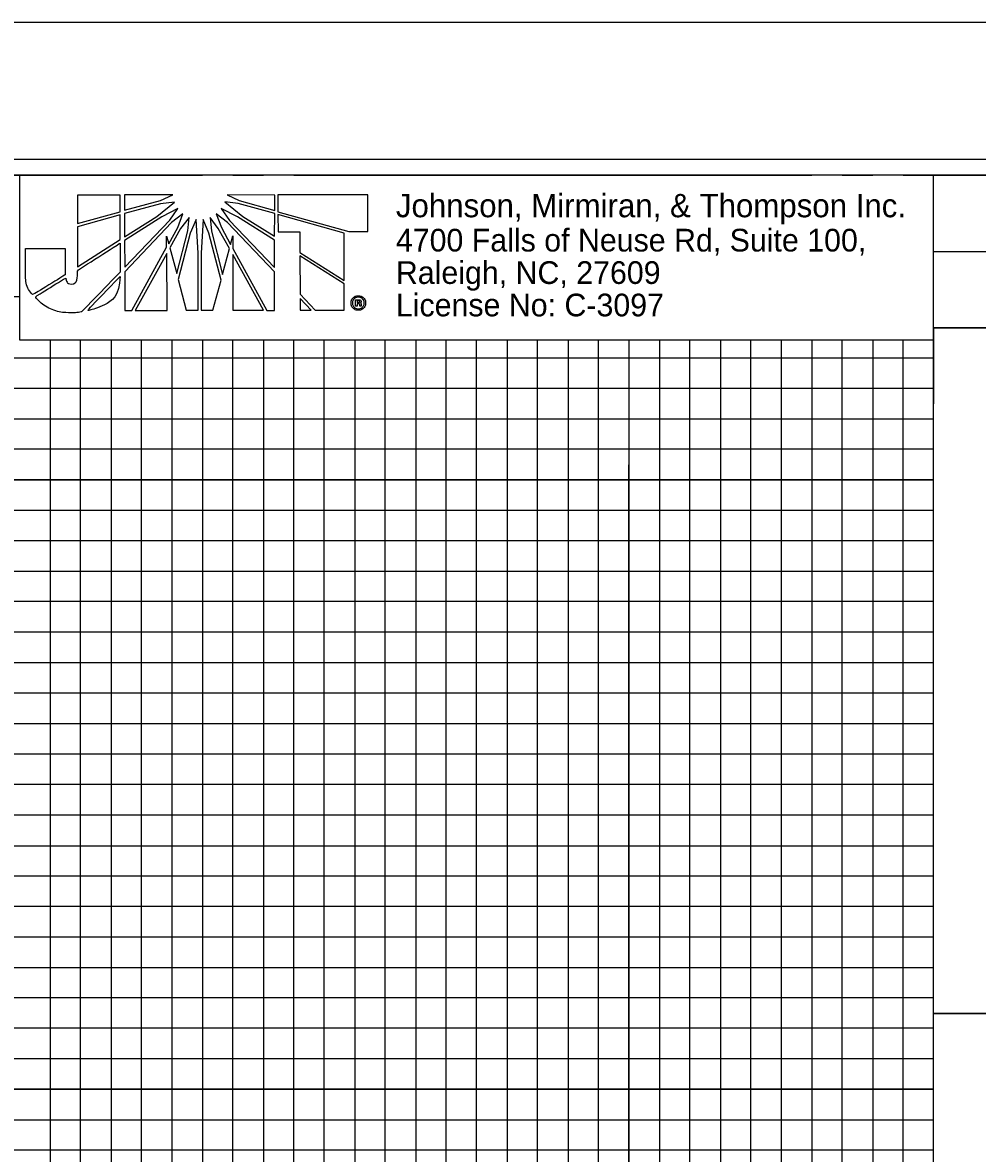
# Model space of a CAD drawing. Extents: x 1650661 to 1652901, y 832691 to 833791.
# Drawn here: x 1652354.8 to 1652511.5, y 833605.5 to 833791 of the extents above; entities that cross this region are included whole.
import ezdxf

# ---------------------------------------------------------------- set-up
doc = ezdxf.new("R2010")
doc.units = 0
for name, color, linetype in [('Prop Dimension Text', 7, 'Continuous'), ('Sheet Cutting Line CELL', 7, 'Continuous'), ('Sheet DOT Grid CELL', 7, 'Continuous'), ('Sheet Plan CELL', 7, 'Continuous'), ('Sheet Plot Border Inside CELL', 7, 'Continuous'), ('Sheet Plot Border Outside CELL', 7, 'Continuous'), ('Sheet Profile CELL', 7, 'Continuous'), ('Sheet Profile Grid Major CELL', 7, 'Continuous'), ('Sheet Profile Grid Middle CELL', 7, 'Continuous'), ('Sheet Profile Grid Minor CELL', 7, 'Continuous'), ('Sheet Sticker Exception Certification CELL', 7, 'Continuous')]:
    doc.layers.add(name, color=color, linetype=linetype)

msp = doc.modelspace()

# ---------------------------------------------------------------- linework, layer by layer
at = {"layer": 'Prop Dimension Text'}
for p, q in [((1652370.79, 833762.71), (1652363.77, 833762.7)), ((1652363.77, 833762.7), (1652363.77, 833758.05)), ((1652370.79, 833760), (1652370.79, 833762.71)), ((1652379.41, 833762.75), (1652371.52, 833762.75)), ((1652371.52, 833762.75), (1652371.52, 833760.23)), ((1652377.4, 833761.86), (1652379.41, 833762.75)), ((1652396.14, 833762.73), (1652388.35, 833762.76)), ((1652388.35, 833762.76), (1652390.32, 833761.84)), ((1652396.14, 833760.21), (1652396.14, 833762.73)), ((1652411.43, 833762.78), (1652396.68, 833762.77)), ((1652396.68, 833762.77), (1652396.68, 833760.06)), ((1652411.44, 833756.74), (1652411.43, 833762.78)), ((1652371.52, 833760.23), (1652377.4, 833761.86)), ((1652377.4, 833761.31), (1652371.52, 833759.69)), ((1652376.79, 833759.23), (1652379.69, 833761.59)), ((1652379.69, 833761.59), (1652377.4, 833761.31)), ((1652380.27, 833760.51), (1652377.6, 833759.15)), ((1652378.92, 833758.61), (1652380.27, 833760.51)), ((1652387.35, 833760.51), (1652388.71, 833758.58)), ((1652390.06, 833759.16), (1652387.35, 833760.51)), ((1652387.96, 833761.6), (1652390.9, 833759.2)), ((1652390.13, 833761.33), (1652387.96, 833761.6)), ((1652396.14, 833759.68), (1652390.13, 833761.33)), ((1652390.32, 833761.84), (1652396.14, 833760.21)), ((1652363.77, 833758.05), (1652370.79, 833760)), ((1652370.79, 833759.49), (1652363.77, 833757.52)), ((1652370.79, 833755.43), (1652370.79, 833759.49)), ((1652371.52, 833759.69), (1652371.52, 833755.89)), ((1652371.52, 833755.89), (1652376.79, 833759.23)), ((1652377.6, 833759.15), (1652371.52, 833755.28)), ((1652381.08, 833759.66), (1652379.22, 833758.22)), ((1652380.23, 833757.42), (1652381.08, 833759.66)), ((1652382.09, 833759.04), (1652380.7, 833757.25)), ((1652381.9, 833756.87), (1652382.09, 833759.04)), ((1652383.25, 833758.73), (1652382.29, 833756.48)), ((1652383.56, 833753.19), (1652383.25, 833758.73)), ((1652384.41, 833758.73), (1652384.05, 833753.19)), ((1652385.34, 833756.48), (1652384.41, 833758.73)), ((1652385.53, 833759.04), (1652385.77, 833756.8)), ((1652386.89, 833757.26), (1652385.53, 833759.04)), ((1652386.53, 833759.67), (1652387.39, 833757.42)), ((1652388.39, 833758.23), (1652386.53, 833759.67)), ((1652396.1, 833755.33), (1652390.06, 833759.16)), ((1652390.9, 833759.2), (1652396.1, 833755.96)), ((1652396.1, 833755.96), (1652396.14, 833759.68)), ((1652396.68, 833760.06), (1652396.68, 833759.98)), ((1652396.68, 833759.98), (1652408.3, 833756.74)), ((1652396.68, 833759.56), (1652396.68, 833759.52)), ((1652407.56, 833756.47), (1652396.68, 833759.56)), ((1652396.68, 833759.52), (1652396.69, 833756.69)), ((1652363.77, 833757.52), (1652363.78, 833750.97)), ((1652371.53, 833750.9), (1652378.92, 833758.61)), ((1652379.22, 833758.22), (1652371.53, 833750.16)), ((1652378.76, 833754.74), (1652380.23, 833757.42)), ((1652380.7, 833757.25), (1652378.96, 833754.08)), ((1652380.09, 833749.87), (1652381.9, 833756.87)), ((1652385.77, 833756.8), (1652387.59, 833749.71)), ((1652388.71, 833753.97), (1652386.89, 833757.26)), ((1652387.39, 833757.42), (1652388.89, 833754.63)), ((1652396.1, 833750.11), (1652388.39, 833758.23)), ((1652388.71, 833758.58), (1652396.1, 833750.84)), ((1652363.78, 833750.97), (1652370.79, 833755.43)), ((1652371.52, 833755.28), (1652371.53, 833750.9)), ((1652378.41, 833754.16), (1652378.41, 833756.01)), ((1652378.41, 833756.01), (1652378.76, 833754.74)), ((1652382.29, 833756.48), (1652380.32, 833748.89)), ((1652387.36, 833748.78), (1652385.34, 833756.48)), ((1652388.89, 833754.63), (1652389.25, 833756.02)), ((1652389.25, 833756.02), (1652389.25, 833753.97)), ((1652396.1, 833750.84), (1652396.1, 833755.33)), ((1652396.69, 833756.69), (1652400.29, 833756.69)), ((1652400.29, 833756.69), (1652400.29, 833753.32)), ((1652407.57, 833748.72), (1652407.56, 833756.47)), ((1652408.3, 833756.74), (1652411.44, 833756.74)), ((1652372.69, 833743.79), (1652378.41, 833754.16)), ((1652378.42, 833753.15), (1652373.24, 833743.79)), ((1652378.47, 833743.8), (1652378.42, 833753.15)), ((1652378.96, 833754.08), (1652380.09, 833749.87)), ((1652383.57, 833743.84), (1652383.56, 833753.19)), ((1652384.05, 833753.19), (1652384.06, 833743.84)), ((1652387.59, 833749.71), (1652388.71, 833753.97)), ((1652389.25, 833753.97), (1652394.87, 833743.81)), ((1652400.29, 833753.32), (1652407.57, 833748.72)), ((1652394.29, 833743.85), (1652389.25, 833752.97)), ((1652389.25, 833752.97), (1652389.26, 833743.84)), ((1652400.29, 833752.74), (1652400.3, 833746.47)), ((1652407.57, 833748.18), (1652400.29, 833752.74)), ((1652371.53, 833750.16), (1652371.53, 833743.79)), ((1652396.11, 833743.81), (1652396.1, 833750.11)), ((1652380.32, 833748.89), (1652381.64, 833743.83)), ((1652386.01, 833743.84), (1652387.36, 833748.78)), ((1652407.57, 833743.82), (1652407.57, 833748.18)), ((1652400.3, 833746.47), (1652402.81, 833743.82)), ((1652402.12, 833743.82), (1652400.3, 833745.78)), ((1652400.3, 833745.78), (1652400.3, 833743.82)), ((1652409.86, 833746.19), (1652409.86, 833745.97)), ((1652409.86, 833745.97), (1652409.86, 833746.19)), ((1652371.53, 833743.79), (1652372.69, 833743.79)), ((1652373.24, 833743.79), (1652378.47, 833743.8)), ((1652381.64, 833743.83), (1652383.57, 833743.84)), ((1652384.06, 833743.84), (1652386.01, 833743.84)), ((1652389.26, 833743.84), (1652394.29, 833743.85)), ((1652394.87, 833743.81), (1652396.11, 833743.81)), ((1652400.3, 833743.82), (1652402.12, 833743.82)), ((1652402.81, 833743.82), (1652407.57, 833743.82)), ((1652409.42, 833744.49), (1652409.42, 833745.56)), ((1652409.42, 833745.56), (1652409.86, 833745.56)), ((1652409.66, 833744.49), (1652409.42, 833744.49)), ((1652409.86, 833745.36), (1652409.66, 833745.36)), ((1652409.66, 833745.36), (1652409.66, 833745.1)), ((1652409.66, 833745.1), (1652409.86, 833745.1)), ((1652409.86, 833744.91), (1652409.66, 833744.91)), ((1652409.66, 833744.91), (1652409.66, 833744.49)), ((1652409.86, 833745.56), (1652409.86, 833745.36)), ((1652409.86, 833745.36), (1652409.86, 833745.56)), ((1652409.86, 833745.56), (1652409.92, 833745.56)), ((1652409.89, 833745.36), (1652409.86, 833745.36)), ((1652409.86, 833745.1), (1652409.86, 833744.91)), ((1652409.86, 833744.91), (1652409.86, 833745.1)), ((1652409.86, 833745.1), (1652409.87, 833745.1)), ((1652409.87, 833744.91), (1652409.86, 833744.91)), ((1652409.86, 833744.07), (1652409.86, 833743.83)), ((1652409.86, 833743.83), (1652409.86, 833744.07)), ((1652409.86, 833744.07), (1652409.87, 833744.07)), ((1652409.87, 833743.83), (1652409.86, 833743.83))]:
    msp.add_line(p, q, dxfattribs=at)
msp.add_lwpolyline([(1652354.28, 833738.96), (1652504.23, 833738.96), (1652504.23, 833766.02), (1652354.28, 833766.02)], close=True, dxfattribs=at)
for points in [[(1652363.77, 833758.05), (1652370.79, 833760), (1652370.79, 833762.71), (1652363.77, 833762.7), (1652363.77, 833758.05)], [(1652377.4, 833761.86), (1652379.41, 833762.75), (1652371.52, 833762.75), (1652371.52, 833760.23), (1652377.4, 833761.86)], [(1652390.32, 833761.84), (1652396.14, 833760.21), (1652396.14, 833762.73), (1652388.35, 833762.76), (1652390.32, 833761.84)], [(1652411.43, 833762.78), (1652396.68, 833762.77), (1652396.68, 833760.06), (1652396.68, 833759.98), (1652408.3, 833756.74), (1652411.44, 833756.74), (1652411.43, 833762.78)], [(1652371.52, 833759.69), (1652371.52, 833755.89), (1652376.79, 833759.23), (1652379.69, 833761.59), (1652377.4, 833761.31), (1652371.52, 833759.69)], [(1652371.52, 833755.28), (1652371.53, 833750.9), (1652378.92, 833758.61), (1652380.27, 833760.51), (1652377.6, 833759.15), (1652371.52, 833755.28)], [(1652387.35, 833760.51), (1652388.71, 833758.58), (1652396.1, 833750.84), (1652396.1, 833755.33), (1652390.06, 833759.16), (1652387.35, 833760.51)], [(1652387.96, 833761.6), (1652390.9, 833759.2), (1652396.1, 833755.96), (1652396.14, 833759.68), (1652390.13, 833761.33), (1652387.96, 833761.6)], [(1652363.78, 833750.97), (1652370.79, 833755.43), (1652370.79, 833759.49), (1652363.77, 833757.52), (1652363.78, 833750.97)], [(1652381.08, 833759.66), (1652379.22, 833758.22), (1652371.53, 833750.16), (1652371.53, 833743.79), (1652372.69, 833743.79), (1652378.41, 833754.16), (1652378.41, 833756.01), (1652378.76, 833754.74), (1652380.23, 833757.42), (1652381.08, 833759.66)], [(1652382.09, 833759.04), (1652380.7, 833757.25), (1652378.96, 833754.08), (1652380.09, 833749.87), (1652381.9, 833756.87), (1652382.09, 833759.04)], [(1652382.29, 833756.48), (1652380.32, 833748.89), (1652381.64, 833743.83), (1652383.57, 833743.84), (1652383.56, 833753.19), (1652383.25, 833758.73), (1652382.29, 833756.48)], [(1652384.41, 833758.73), (1652384.05, 833753.19), (1652384.06, 833743.84), (1652386.01, 833743.84), (1652387.36, 833748.78), (1652385.34, 833756.48), (1652384.41, 833758.73)], [(1652385.53, 833759.04), (1652385.77, 833756.8), (1652387.59, 833749.71), (1652388.71, 833753.97), (1652386.89, 833757.26), (1652385.53, 833759.04)], [(1652386.53, 833759.67), (1652387.39, 833757.42), (1652388.89, 833754.63), (1652389.25, 833756.02), (1652389.25, 833753.97), (1652394.87, 833743.81), (1652396.11, 833743.81), (1652396.1, 833750.11), (1652388.39, 833758.23), (1652386.53, 833759.67)], [(1652396.68, 833759.56), (1652396.68, 833759.52), (1652396.69, 833756.69), (1652400.29, 833756.69), (1652400.29, 833753.32), (1652407.57, 833748.72), (1652407.56, 833756.47), (1652396.68, 833759.56)], [(1652373.24, 833743.79), (1652378.47, 833743.8), (1652378.42, 833753.15), (1652373.24, 833743.79)], [(1652389.26, 833743.84), (1652394.29, 833743.85), (1652389.25, 833752.97), (1652389.26, 833743.84)], [(1652400.29, 833752.74), (1652400.3, 833746.47), (1652402.81, 833743.82), (1652407.57, 833743.82), (1652407.57, 833748.18), (1652400.29, 833752.74), (1652400.29, 833752.74)], [(1652400.3, 833743.82), (1652400.3, 833743.82), (1652402.12, 833743.82), (1652400.3, 833745.78), (1652400.3, 833743.82)], [(1652410.33, 833744.74), (1652410.33, 833744.68), (1652410.33, 833744.64), (1652410.33, 833744.61), (1652410.36, 833744.49), (1652410.14, 833744.49)]]:
    msp.add_lwpolyline(points, dxfattribs=at)
for points, degree in [([(1652361.76, 833753.98), (1652361.76, 833753.98), (1652355.27, 833753.98), (1652355.27, 833753.98), (1652355.27, 833753.98), (1652355.27, 833749.91), (1652355.27, 833749.91), (1652355.27, 833749.91), (1652355.27, 833749.48), (1652355.27, 833749.48), (1652355.27, 833748.21), (1652355.69, 833747.2), (1652356.43, 833746.36), (1652356.43, 833746.36), (1652361.77, 833749.6), (1652361.77, 833749.69), (1652361.77, 833749.69), (1652361.76, 833753.98), (1652361.76, 833753.98)], 3), ([(1652362.78, 833748.13), (1652362.36, 833748.13), (1652362, 833748.37), (1652361.85, 833749.14), (1652361.85, 833749.14), (1652356.81, 833746.02), (1652356.81, 833746.02), (1652358.37, 833744.39), (1652360.85, 833743.42), (1652362.94, 833743.42), (1652363.49, 833743.42), (1652363.9, 833743.47), (1652364.48, 833743.59), (1652364.48, 833743.59), (1652370.8, 833750.12), (1652370.8, 833750.12), (1652370.8, 833750.12), (1652370.79, 833754.85), (1652370.79, 833754.85), (1652370.79, 833754.85), (1652363.78, 833750.38), (1652363.78, 833750.38), (1652363.78, 833748.61), (1652363.35, 833748.14), (1652362.78, 833748.13)], 3), ([(1652362.78, 833748.13), (1652362.36, 833748.13), (1652362, 833748.37), (1652361.85, 833749.14), (1652361.85, 833749.14), (1652356.81, 833746.02), (1652356.81, 833746.02), (1652358.37, 833744.39), (1652360.85, 833743.42), (1652362.94, 833743.42), (1652363.49, 833743.42), (1652363.9, 833743.47), (1652364.48, 833743.59), (1652364.48, 833743.59), (1652370.8, 833750.12), (1652370.8, 833750.12), (1652370.8, 833750.12), (1652370.79, 833754.85), (1652370.79, 833754.85), (1652370.79, 833754.85), (1652363.78, 833750.38), (1652363.78, 833750.38), (1652363.78, 833748.61), (1652363.35, 833748.14), (1652362.78, 833748.13)], 3), ([(1652370.8, 833749.38), (1652370.8, 833749.38), (1652365.34, 833743.74), (1652365.34, 833743.74), (1652368.01, 833744.4), (1652370.68, 833746.17), (1652370.8, 833749.38)], 3), ([(1652409.86, 833743.83), (1652409.54, 833743.83), (1652409.25, 833743.95), (1652409.02, 833744.18), (1652408.78, 833744.41), (1652408.67, 833744.69), (1652408.67, 833745.02), (1652408.67, 833745.35), (1652408.78, 833745.64), (1652409.02, 833745.85), (1652409.25, 833746.08), (1652409.52, 833746.19), (1652409.86, 833746.19)], 3), ([(1652409.86, 833745.97), (1652409.59, 833745.97), (1652409.37, 833745.88), (1652409.18, 833745.71), (1652409, 833745.52), (1652408.9, 833745.29), (1652408.9, 833745.02), (1652408.9, 833744.76), (1652409, 833744.53), (1652409.18, 833744.34), (1652409.37, 833744.16), (1652409.59, 833744.07), (1652409.86, 833744.07)], 3), ([(1652409.86, 833746.19), (1652410.19, 833746.19), (1652410.47, 833746.08), (1652410.7, 833745.85), (1652410.94, 833745.64), (1652411.06, 833745.36), (1652411.06, 833745.03)], 3), ([(1652409.87, 833744.07), (1652410.13, 833744.07), (1652410.35, 833744.16), (1652410.54, 833744.34), (1652410.72, 833744.53), (1652410.82, 833744.76), (1652410.82, 833745.03), (1652410.82, 833745.29), (1652410.72, 833745.52), (1652410.54, 833745.71), (1652410.35, 833745.88), (1652410.13, 833745.97), (1652409.86, 833745.97)], 3), ([(1652409.87, 833745.1), (1652410.02, 833745.1), (1652410.1, 833745.15), (1652410.1, 833745.24), (1652410.1, 833745.32), (1652410.03, 833745.36), (1652409.89, 833745.36)], 3), ([(1652411.06, 833745.03), (1652411.06, 833744.69), (1652410.94, 833744.41), (1652410.72, 833744.18), (1652410.48, 833743.95), (1652410.2, 833743.83), (1652409.87, 833743.83)], 3), ([(1652410.05, 833744.87), (1652410.02, 833744.89), (1652409.96, 833744.91), (1652409.87, 833744.91)], 2), ([(1652409.92, 833745.56), (1652410.2, 833745.56), (1652410.33, 833745.45), (1652410.33, 833745.24), (1652410.33, 833745.14), (1652410.3, 833745.06), (1652410.21, 833745)], 3), ([(1652410.14, 833744.49), (1652410.11, 833744.55), (1652410.09, 833744.61), (1652410.09, 833744.68), (1652410.09, 833744.78), (1652410.08, 833744.84), (1652410.05, 833744.87)], 3), ([(1652410.21, 833745), (1652410.28, 833744.97), (1652410.32, 833744.88), (1652410.33, 833744.74)], 2)]:
    msp.add_open_spline(points, degree=degree, dxfattribs=at)
at = {"layer": 'Sheet Cutting Line CELL'}
msp.add_line((1652721.28, 833791.02), (1651037.28, 833791.02), dxfattribs=at)
at = {"layer": 'Sheet DOT Grid CELL'}
for p, q in [((1652404.28, 833266.02), (1652404.28, 833718.48)), ((1652454.28, 833266.02), (1652454.28, 833718.48)), ((1652504.23, 833716.02), (1651204.28, 833716.02)), ((1652504.23, 833666.02), (1651204.28, 833666.02)), ((1652504.28, 833266.02), (1652504.28, 833628.47)), ((1652504.28, 833616.02), (1651204.28, 833616.02))]:
    msp.add_line(p, q, dxfattribs=at)
at = {"layer": 'Sheet Plan CELL'}
msp.add_line((1652504.23, 833740.94), (1652504.23, 833728.45), dxfattribs=at)
msp.add_line((1652504.23, 833740.94), (1652504.23, 833728.45), dxfattribs=at)
msp.add_line((1652504.23, 833740.94), (1652504.23, 833728.45), dxfattribs=at)
at = {"layer": 'Sheet Plot Border Inside CELL'}
msp.add_lwpolyline([(1651050.28, 832713.47), (1652716.78, 832713.47), (1652716.78, 833768.57), (1651050.28, 833768.57)], close=True, dxfattribs=at)
at = {"layer": 'Sheet Plot Border Outside CELL'}
msp.add_lwpolyline([(1651037.28, 832691.02), (1652721.28, 832691.02), (1652721.28, 833791.02), (1651037.28, 833791.02)], close=True, dxfattribs=at)
at = {"layer": 'Sheet Profile CELL'}
msp.add_line((1652504.23, 833753.47), (1652704.28, 833753.47), dxfattribs=at)
for points in [[(1652704.28, 833766.02), (1651204.28, 833766.02), (1651204.28, 832716.02), (1652704.28, 832716.02)], [(1652504.23, 833766.02), (1652704.28, 833766.02), (1652704.28, 833740.97), (1652504.23, 833740.97)], [(1652504.23, 833740.97), (1652604.28, 833740.97), (1652604.28, 833628.47), (1652504.23, 833628.47)]]:
    msp.add_lwpolyline(points, close=True, dxfattribs=at)
at = {"layer": 'Sheet Profile Grid Major CELL'}
for points in [[(1652404.28, 833766.02), (1652454.28, 833766.02)], [(1652454.28, 833738.96), (1652454.28, 833266.02), (1652504.28, 833266.02), (1652504.28, 833766.02), (1652530.58, 833766.02)], [(1652354.28, 833266.02), (1652404.28, 833266.02), (1652404.28, 833738.96)], [(1651204.28, 833716.02), (1652504.28, 833716.02)], [(1652504.28, 833666.02), (1651204.28, 833666.02), (1651204.28, 833616.02), (1652504.28, 833616.02)]]:
    msp.add_lwpolyline(points, dxfattribs=at)
at = {"layer": 'Sheet Profile Grid Middle CELL'}
for points in [[(1652329.28, 833766.02), (1652379.28, 833766.02)], [(1652429.28, 833766.02), (1652479.28, 833766.02)], [(1652379.28, 833738.96), (1652379.28, 833266.02), (1652429.28, 833266.02), (1652429.28, 833738.96)], [(1652479.28, 833738.96), (1652479.28, 833266.02), (1652529.28, 833266.02), (1652529.28, 833604.97)], [(1652504.28, 833691.02), (1651204.28, 833691.02), (1651204.28, 833641.02), (1652504.28, 833641.02)]]:
    msp.add_lwpolyline(points, dxfattribs=at)
at = {"layer": 'Sheet Profile Grid Minor CELL'}
for p, q in [((1652504.23, 833761.02), (1652504.28, 833761.02)), ((1652504.28, 833756.02), (1652504.23, 833756.02)), ((1652504.23, 833751.02), (1652504.28, 833751.02)), ((1652504.23, 833631.02), (1651254.28, 833631.02)), ((1652504.28, 833626.02), (1651254.28, 833626.02)), ((1652504.28, 833621.02), (1651254.28, 833621.02)), ((1651254.28, 833611.02), (1652504.28, 833611.02)), ((1652504.28, 833606.02), (1651254.28, 833606.02))]:
    msp.add_line(p, q, dxfattribs=at)
for points in [[(1652349.28, 833766.02), (1652359.28, 833766.02)], [(1652364.28, 833766.02), (1652369.28, 833766.02)], [(1652374.28, 833766.02), (1652384.28, 833766.02)], [(1652389.28, 833766.02), (1652394.28, 833766.02)], [(1652399.28, 833766.02), (1652409.28, 833766.02)], [(1652414.28, 833766.02), (1652419.28, 833766.02)], [(1652424.28, 833766.02), (1652434.28, 833766.02)], [(1652439.28, 833766.02), (1652444.28, 833766.02)], [(1652449.28, 833766.02), (1652459.28, 833766.02)], [(1652464.28, 833766.02), (1652469.28, 833766.02)], [(1652474.28, 833766.02), (1652484.28, 833766.02)], [(1652489.28, 833766.02), (1652494.28, 833766.02)], [(1652499.28, 833766.02), (1652509.28, 833766.02)], [(1652354.28, 833746.02), (1651254.28, 833746.02), (1651254.28, 833736.02), (1652504.28, 833736.02)], [(1652504.28, 833746.02), (1652504.23, 833746.02)], [(1652359.28, 833738.96), (1652359.28, 833266.02), (1652364.28, 833266.02), (1652364.28, 833738.96)], [(1652369.28, 833738.96), (1652369.28, 833266.02), (1652374.28, 833266.02), (1652374.28, 833738.96)], [(1652384.28, 833738.96), (1652384.28, 833266.02), (1652389.28, 833266.02), (1652389.28, 833738.96)], [(1652394.28, 833266.02), (1652399.28, 833266.02), (1652399.28, 833738.96)], [(1652394.28, 833738.96), (1652394.28, 833266.02)], [(1652409.28, 833738.96), (1652409.28, 833266.02), (1652414.28, 833266.02), (1652414.28, 833738.96)], [(1652419.28, 833738.96), (1652419.28, 833266.02), (1652424.28, 833266.02), (1652424.28, 833738.96)], [(1652434.28, 833738.96), (1652434.28, 833266.02), (1652439.28, 833266.02), (1652439.28, 833738.96)], [(1652444.28, 833738.96), (1652444.28, 833266.02), (1652449.28, 833266.02), (1652449.28, 833738.96)], [(1652459.28, 833738.96), (1652459.28, 833266.02), (1652464.28, 833266.02), (1652464.28, 833738.96)], [(1652469.28, 833738.96), (1652469.28, 833266.02), (1652474.28, 833266.02), (1652474.28, 833738.96)], [(1652484.28, 833738.96), (1652484.28, 833266.02), (1652489.28, 833266.02), (1652489.28, 833738.96)], [(1652494.28, 833738.96), (1652494.28, 833266.02), (1652499.28, 833266.02), (1652499.28, 833738.96)], [(1652504.23, 833731.02), (1651254.28, 833731.02), (1651254.28, 833726.02), (1652504.28, 833726.02)], [(1652504.28, 833721.02), (1651254.28, 833721.02), (1651254.28, 833711.02), (1652504.28, 833711.02)], [(1652504.28, 833706.02), (1651254.28, 833706.02), (1651254.28, 833701.02), (1652504.28, 833701.02)], [(1652504.28, 833696.02), (1651254.28, 833696.02), (1651254.28, 833686.02), (1652504.28, 833686.02)], [(1652504.28, 833681.02), (1651254.28, 833681.02), (1651254.28, 833676.02), (1652504.28, 833676.02)], [(1652504.28, 833671.02), (1651254.28, 833671.02), (1651254.28, 833661.02), (1652504.28, 833661.02)], [(1652504.28, 833655.92), (1651254.38, 833655.92), (1651254.38, 833651.02), (1652504.28, 833651.02)], [(1652504.28, 833646.02), (1651254.28, 833646.02), (1651254.28, 833636.02), (1652504.28, 833636.02)]]:
    msp.add_lwpolyline(points, dxfattribs=at)
at = {"layer": 'Sheet Sticker Exception Certification CELL'}
for p, q in [((1652504.23, 833604.97), (1652504.23, 833628.47)), ((1652504.23, 833628.47), (1652704.27, 833628.47)), ((1652504.23, 833604.97), (1652504.23, 833628.47)), ((1652504.23, 833628.47), (1652704.27, 833628.47))]:
    msp.add_line(p, q, dxfattribs=at)

# ---------------------------------------------------------------- texts
at = {"layer": 'Prop Dimension Text'}
for s, height, p in [('Johnson, Mirmiran, & Thompson Inc.', 3.8315, (1652416.03, 833759.09)), ('4700 Falls of Neuse Rd, Suite 100, ', 3.722, (1652416.03, 833753.47)), ('Raleigh, NC, 27609', 3.722, (1652416.03, 833748.15)), ('License No: C-3097', 3.722, (1652416.03, 833742.83))]:
    msp.add_text(s, height=height, rotation=360, dxfattribs=at).set_placement(p)

doc.saveas('drawing.dxf')
